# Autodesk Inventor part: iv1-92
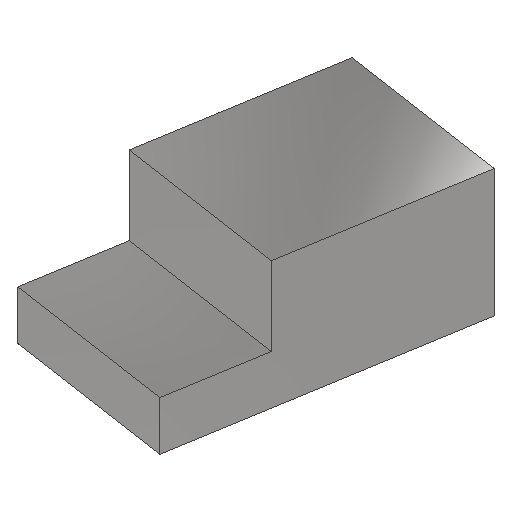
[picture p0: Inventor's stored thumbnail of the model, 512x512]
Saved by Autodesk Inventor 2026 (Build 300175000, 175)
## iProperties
Created: 2004-09
Part Number: iv1-92
Document SubType Name: Modeling
Designer: Lars Bertram Pedersen
Manufacturer: Standard
Standards Organization: Custom
Material: Steel, Mild
Density: 7.85 g/cm^3
Appearance: Semi-Polished
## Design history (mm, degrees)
sketch "Sketch1"
  geometry: L1 (-60, 0)-(0, 0); L2 (0, 0)-(0, 10); L3 (0, 10)-(-20, 10); L4 (-20, 10)-(-20, 26); L5 (-20, 26)-(-60, 26); L6 (-60, 26)-(-60, 0); 1 further point
  constraints: 12 end point, 3 perpendicular, 2 parallel, 1 coincident, 1 horizontal
  dimensions: "d0" = 60 distance of L1.start L1.end; "d1" = 10 distance of L1.end L2.end; "d2" = 16 distance of L3.end L4.end; "d3" = 40 distance of L4.end L5.end
extrude "Extrusion1" new body sketch "Sketch1" distance "d4" = 35; taper "d5" = 0 deg
body "Solid1"
